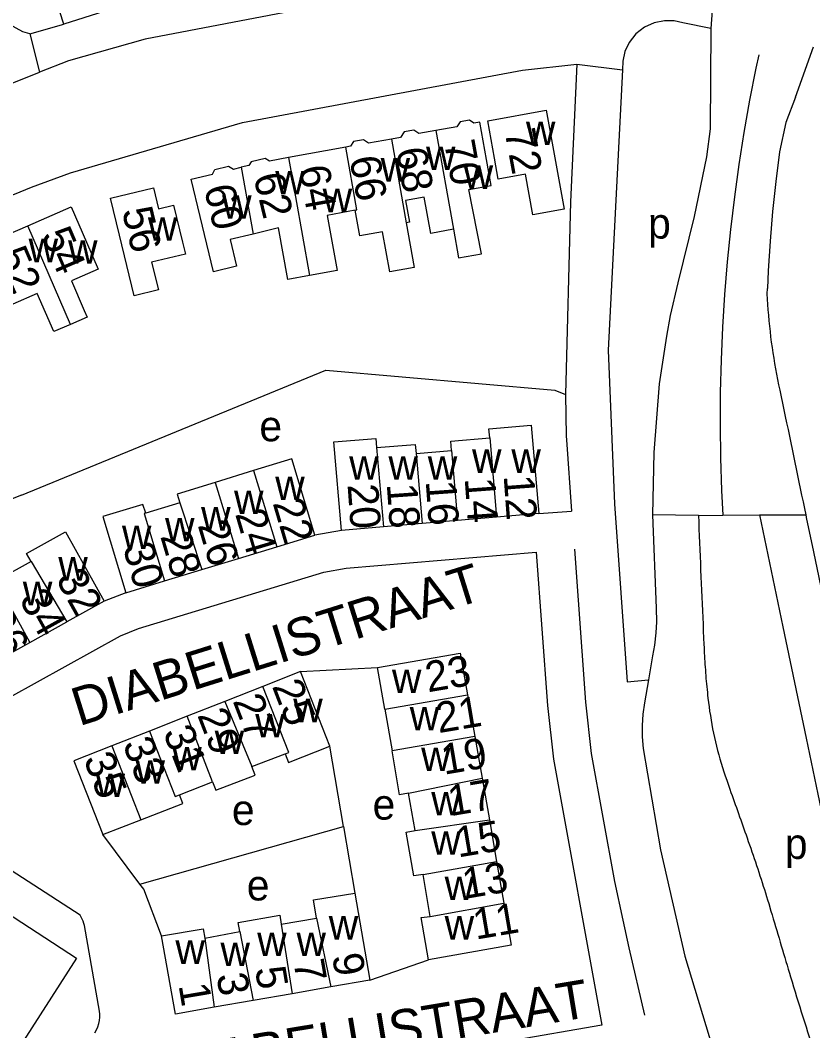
# Model space of a CAD drawing. Extents: x 159045 to 160918, y 380454 to 382516.
# Drawn here: x 160420.2 to 160524.1, y 381588.1 to 381720.5 of the extents above; entities that cross this region are included whole.
import ezdxf

# ---------------------------------------------------------------- set-up
doc = ezdxf.new("R2010")
doc.units = 0
for name, color, linetype in [('BLT_Basislijn', 7, 'Continuous'), ('BLT_Bebouwing', 7, 'Continuous'), ('BLT_Centroide', 7, 'Continuous'), ('BLT_Huisnummer', 7, 'Continuous'), ('BLT_Huisnummer_ tussenligend', 7, 'Continuous'), ('BLT_Onderverdeling_panden', 7, 'Continuous'), ('BLT_Straatnaam', 7, 'Continuous'), ('BLT_Vlakafsluiter', 7, 'Continuous')]:
    doc.layers.add(name, color=color, linetype=linetype)

msp = doc.modelspace()

# ---------------------------------------------------------------- linework, layer by layer
at = {"layer": 'BLT_Basislijn'}
for p, q in [((160510.75, 381719.44), (160507.06, 381720.16)), ((160421.42, 381718.73), (160422.69, 381713.7)), ((160521.87, 381710.43), (160524.19, 381717.05)), ((160491.67, 381671.47), (160491.79, 381666)), ((160503.25, 381663.87), (160503.08, 381655.7)), ((160488.18, 381655.86), (160492.48, 381656.18)), ((160509.11, 381655.6), (160512.3, 381655.63)), ((160512.3, 381655.63), (160517.12, 381655.67)), ((160462.29, 381653.66), (160458.83, 381653.04)), ((160434.02, 381645.49), (160431.17, 381644.36)), ((160456.94, 381635.14), (160467.03, 381635.68)), ((160502.58, 381634.08), (160502.03, 381631.05)), ((160502.03, 381631.05), (160501.84, 381629.56)), ((160378.5, 381629.28), (160427.57, 381597.58)), ((160501.84, 381629.56), (160501.74, 381628.07)), ((160501.74, 381628.07), (160501.73, 381626.58)), ((160501.73, 381626.58), (160501.85, 381625.08)), ((160462.58, 381614.83), (160460.78, 381625.37)), ((160435.88, 381607.3), (160462.58, 381614.83)), ((160462.58, 381614.83), (160464.08, 381606.11)), ((160498.12, 381607.65), (160499.22, 381602.56)), ((160427.57, 381597.58), (160417.9, 381582.6)), ((160466.03, 381594.7), (160473.73, 381597.38))]:
    msp.add_line(p, q, dxfattribs=at)
for points in [[(160421.42, 381718.73), (160420.52, 381718.98), (160408.42, 381725.7)], [(160463.62, 381723.22), (160463.38, 381723.18), (160436.55, 381718.05), (160426.52, 381715.2), (160422.69, 381713.7)], [(160421.42, 381718.73), (160425.89, 381719.98)], [(160507.06, 381720.16), (160505.92, 381720.42), (160504.65, 381720.45), (160503.33, 381720.18), (160502.05, 381719.6), (160500.92, 381718.72), (160500.05, 381717.62), (160499.47, 381716.4), (160499.19, 381715.17), (160499.16, 381714)], [(160510.75, 381719.44), (160510.64, 381706.3), (160510.17, 381702.62), (160508.56, 381694.79), (160506.43, 381686.1), (160505.43, 381681.83), (160504.93, 381679.13), (160503.97, 381672.88), (160503.25, 381663.87)], [(160517.02, 381715.99), (160516.64, 381714.23), (160515.82, 381710.03), (160515.08, 381705.81), (160514.41, 381701.59), (160513.83, 381697.35), (160513.32, 381693.09), (160512.9, 381688.84), (160512.55, 381684.57), (160512.28, 381680.3), (160512.09, 381676.02), (160511.99, 381671.74), (160511.96, 381667.46), (160512.01, 381663.18), (160512.15, 381658.9), (160512.3, 381655.63)], [(160343.13, 381655.19), (160349.63, 381659.57), (160374.12, 381676.49), (160389.16, 381685.3), (160421.65, 381698.65), (160426.75, 381700.5), (160449.33, 381707.1), (160486.03, 381713.96), (160493.16, 381714.78)], [(160493.16, 381714.78), (160492.34, 381696.72), (160491.67, 381671.47)], [(160373.77, 381692), (160385.73, 381698.91), (160422.69, 381713.7)], [(160499.16, 381714), (160497.27, 381677.29), (160498.11, 381657.12), (160499.79, 381633.79), (160502.58, 381634.08)], [(160521.87, 381710.43), (160520.56, 381707.13), (160519.74, 381703.25), (160519.26, 381699.36), (160518.85, 381695.47), (160518.52, 381691.56), (160518.27, 381687.65), (160518.17, 381685.37)], [(160519.83, 381672.03), (160519.68, 381672.73), (160519.54, 381673.42), (160519.4, 381674.11), (160519.27, 381674.81), (160519.15, 381675.51), (160519.03, 381676.21), (160518.92, 381676.91), (160518.82, 381677.61), (160518.72, 381678.31), (160518.63, 381679.02), (160518.55, 381679.72), (160518.47, 381680.43), (160518.4, 381681.13), (160518.34, 381681.84), (160518.28, 381682.55), (160518.23, 381683.25), (160518.19, 381683.96), (160518.15, 381684.67), (160518.17, 381685.37)], [(160420.33, 381658.28), (160460.24, 381674.67), (160490.28, 381672.01), (160491.67, 381671.47)], [(160523.24, 381655.68), (160523.06, 381656.54), (160522.88, 381657.4), (160522.7, 381658.26), (160522.52, 381659.13), (160522.34, 381659.99), (160522.16, 381660.85), (160521.98, 381661.71), (160521.8, 381662.57), (160521.62, 381663.43), (160521.45, 381664.29), (160521.27, 381665.15), (160521.09, 381666.01), (160520.91, 381666.87), (160520.73, 381667.73), (160520.55, 381668.59), (160520.37, 381669.45), (160520.19, 381670.31), (160520.01, 381671.17), (160519.83, 381672.03)], [(160491.79, 381666), (160491.8, 381665.54), (160492.48, 381656.18)], [(160420.33, 381658.28), (160407.99, 381653.36), (160398.29, 381648.34), (160390.1, 381643.2)], [(160503.08, 381655.7), (160503.57, 381643.44), (160503.62, 381641.68), (160503.53, 381640.24), (160503.36, 381638.59), (160503.09, 381637.23), (160502.58, 381634.08)], [(160509.11, 381655.6), (160509.15, 381654.71), (160509.19, 381653.82), (160509.22, 381652.93), (160509.26, 381652.04), (160509.3, 381651.14), (160509.34, 381650.25), (160509.38, 381649.36), (160509.41, 381648.47), (160509.45, 381647.58), (160509.49, 381646.69), (160509.53, 381645.8), (160509.57, 381644.91), (160509.61, 381644.02), (160509.64, 381643.13), (160509.68, 381642.24), (160509.72, 381641.35), (160509.76, 381640.46), (160509.8, 381639.57), (160509.84, 381638.68)], [(160517.12, 381655.67), (160518.65, 381648.35), (160520.18, 381641.03), (160521.71, 381633.72), (160523.24, 381626.4), (160524.77, 381619.09), (160526.3, 381611.77), (160527.13, 381607.83)], [(160532.93, 381609.3), (160532.82, 381609.86), (160532.7, 381610.42), (160532.58, 381610.98), (160532.47, 381611.54), (160532.35, 381612.1), (160532.23, 381612.67), (160531.26, 381617.32), (160529.86, 381624.02), (160528.46, 381630.72), (160527.06, 381637.42), (160525.66, 381644.12), (160524.26, 381650.83), (160523.31, 381655.33), (160523.29, 381655.46), (160523.26, 381655.58), (160523.24, 381655.68)], [(160492.85, 381651.18), (160494.32, 381631.15), (160495.06, 381624.39), (160498.12, 381607.65)], [(160386.88, 381639.33), (160407.89, 381625.76), (160433.31, 381639.83), (160435.69, 381640.78), (160460.01, 381648.17), (160462.92, 381648.69), (160487.86, 381650.82), (160489.34, 381630.7), (160490.11, 381623.67), (160496.47, 381588.81), (160472.24, 381584.61), (160444.49, 381579.75), (160425.82, 381576.36), (160425.81, 381576.36), (160423.42, 381575.08), (160418.36, 381568.45)], [(160509.84, 381638.68), (160509.85, 381638.31), (160509.87, 381637.94), (160509.89, 381637.57), (160509.91, 381637.2), (160509.93, 381636.83), (160509.95, 381636.47), (160509.97, 381636.1), (160510, 381635.73), (160510.03, 381635.36), (160510.05, 381634.99), (160510.08, 381634.62), (160510.11, 381634.25), (160510.15, 381633.89), (160510.18, 381633.52), (160510.22, 381633.15), (160510.25, 381632.78), (160510.29, 381632.42), (160510.33, 381632.05), (160510.37, 381631.68)], [(160429.96, 381587.81), (160430.18, 381588.2), (160430.35, 381588.6), (160430.47, 381589.02), (160430.56, 381589.43), (160430.61, 381589.85), (160430.61, 381590.26), (160430.58, 381590.65), (160428.59, 381601.85), (160428.53, 381602.14), (160428.44, 381602.43), (160428.32, 381602.71), (160428.19, 381602.98), (160428.03, 381603.24), (160381.73, 381633.15)], [(160510.37, 381631.68), (160510.44, 381631.1), (160510.51, 381630.53), (160510.59, 381629.95), (160510.68, 381629.38), (160510.77, 381628.8), (160510.88, 381628.23), (160510.98, 381627.65), (160511.1, 381627.08), (160511.22, 381626.51), (160511.35, 381625.95), (160511.49, 381625.38), (160511.63, 381624.81), (160511.78, 381624.25), (160511.94, 381623.69), (160512.1, 381623.13), (160512.27, 381622.58), (160512.45, 381622.02), (160512.64, 381621.47), (160512.83, 381620.92)], [(160501.85, 381625.08), (160504.13, 381611.77), (160507.35, 381597.84)], [(160512.83, 381620.92), (160512.97, 381620.52), (160513.11, 381620.12), (160513.25, 381619.72), (160513.39, 381619.32), (160513.53, 381618.92), (160513.67, 381618.53), (160513.81, 381618.13), (160513.95, 381617.73), (160514.1, 381617.33), (160514.24, 381616.93), (160514.38, 381616.53), (160514.52, 381616.13), (160514.66, 381615.73), (160514.8, 381615.33), (160514.94, 381614.93), (160515.08, 381614.53), (160515.22, 381614.13), (160515.36, 381613.74), (160515.51, 381613.34)], [(160435.88, 381607.3), (160431.02, 381613.79)], [(160515.51, 381613.34), (160515.66, 381612.89), (160515.82, 381612.44), (160515.98, 381611.99), (160516.13, 381611.54), (160516.29, 381611.09), (160516.44, 381610.64), (160516.59, 381610.2), (160516.74, 381609.74), (160516.89, 381609.29), (160517.04, 381608.84), (160517.19, 381608.39), (160517.34, 381607.94), (160517.48, 381607.49), (160517.63, 381607.04), (160517.77, 381606.58), (160517.91, 381606.13), (160518.05, 381605.68), (160518.19, 381605.22), (160518.33, 381604.77)], [(160438.72, 381600.52), (160436.39, 381606.63), (160435.88, 381607.3)], [(160518.33, 381604.77), (160518.63, 381603.75), (160518.78, 381603.25), (160518.93, 381602.74), (160519.08, 381602.23), (160519.24, 381601.73), (160519.39, 381601.22), (160519.54, 381600.71), (160519.69, 381600.21), (160519.84, 381599.7), (160519.99, 381599.19), (160520.14, 381598.68), (160520.29, 381598.18), (160520.44, 381597.67), (160520.59, 381597.16), (160520.74, 381596.66), (160520.9, 381596.15), (160521.05, 381595.64), (160521.2, 381595.14)], [(160499.22, 381602.56), (160500, 381598.96), (160502.04, 381590.1)], [(160507.35, 381597.84), (160513.26, 381578.22), (160519.72, 381558.71)], [(160521.2, 381595.14), (160521.4, 381594.48), (160521.6, 381593.82), (160521.8, 381593.16), (160522, 381592.5), (160522.2, 381591.85), (160522.41, 381591.19), (160522.61, 381590.54), (160522.82, 381589.88), (160523.03, 381589.22), (160523.23, 381588.57), (160523.44, 381587.91), (160523.65, 381587.26), (160523.86, 381586.6), (160524.07, 381585.95), (160524.28, 381585.3), (160524.5, 381584.64), (160524.71, 381583.99), (160524.93, 381583.34), (160525.61, 381581.26)]]:
    msp.add_lwpolyline(points, dxfattribs=at)
at = {"layer": 'BLT_Bebouwing'}
for p, q in [((160462.86, 381703.88), (160455.38, 381702.52)), ((160415.8, 381691.26), (160421.19, 381693.58)), ((160470.81, 381693.96), (160471.86, 381688.12)), ((160472.09, 381663.74), (160476.74, 381664.14)), ((160450.78, 381661.49), (160445.76, 381659.95)), ((160441.09, 381657.27), (160436.64, 381655.92)), ((160477.52, 381654.95), (160472.87, 381654.56)), ((160482.64, 381655.39), (160477.52, 381654.95)), ((160472.87, 381654.56), (160467.8, 381654.12)), ((160448.8, 381649.99), (160453.81, 381651.51)), ((160421.6, 381649.59), (160416.99, 381647.03)), ((160443.98, 381648.52), (160448.8, 381649.99)), ((160439.11, 381647.04), (160443.98, 381648.52)), ((160431.17, 381644.36), (160426.31, 381641.67)), ((160421.45, 381638.98), (160426.31, 381641.67)), ((160416.6, 381636.29), (160421.45, 381638.98)), ((160451.98, 381633.19), (160447.03, 381631.24)), ((160447.03, 381631.24), (160442.08, 381629.3)), ((160478.83, 381632.1), (160479.79, 381626.63)), ((160467.98, 381630.22), (160468.94, 381624.75)), ((160442.08, 381629.3), (160437.13, 381627.35)), ((160437.13, 381627.35), (160432.18, 381625.41)), ((160479.79, 381626.63), (160480.74, 381621.17)), ((160450.55, 381622.69), (160454.91, 381624.36)), ((160441.05, 381618.99), (160445.39, 381620.68)), ((160480.74, 381621.17), (160481.7, 381615.71)), ((160481.7, 381615.71), (160482.65, 381610.24)), ((160482.65, 381610.24), (160483.61, 381604.78)), ((160473.92, 381603.06), (160473, 381608.57)), ((160454.42, 381602.03), (160459.02, 381602.85)), ((160444.39, 381600.21), (160448.98, 381601.06)), ((160455.83, 381592.92), (160450.72, 381592.04)), ((160460.93, 381593.81), (160455.83, 381592.92)), ((160450.72, 381592.04), (160445.62, 381591.15))]:
    msp.add_line(p, q, dxfattribs=at)
for points in [[(160425.89, 381719.98), (160424.38, 381724.75), (160423.3, 381728.18)], [(160431.37, 381721.7), (160431.14, 381721.64), (160425.89, 381719.98)], [(160487.41, 381695.02), (160486.45, 381700.33), (160482.87, 381699.67), (160482.37, 381702.43), (160481.48, 381707.35), (160489.16, 381708.75), (160491.52, 381695.77), (160487.41, 381695.02)], [(160477.02, 381693.12), (160477.65, 381689.37), (160480.68, 381689.92), (160478.99, 381698.32), (160481.95, 381698.85), (160481.33, 381702.26), (160480.43, 381707.17), (160479.68, 381707.04), (160479.09, 381707.44), (160477.88, 381707.22), (160477.42, 381706.56), (160474.7, 381706.06)], [(160474.7, 381706.06), (160472.46, 381705.65), (160471.8, 381706.11), (160470.52, 381705.88), (160470.03, 381705.16), (160468.88, 381704.95)], [(160468.88, 381704.95), (160465.87, 381704.4), (160465.21, 381704.86), (160463.9, 381704.62), (160463.47, 381703.99), (160462.86, 381703.88)], [(160455.38, 381702.52), (160452.85, 381702.06), (160452.28, 381702.41), (160450.46, 381701.97), (160450.14, 381701.49), (160449.14, 381701.25)], [(160450.71, 381692.49), (160447.69, 381691.76), (160448.54, 381688.27), (160445.54, 381687.54), (160443.77, 381694.81), (160442.6, 381699.67), (160445.41, 381700.35), (160445.7, 381700.95), (160447.51, 381701.39), (160448.13, 381701), (160449.14, 381701.25)], [(160441.47, 381691.43), (160441.85, 381689.86), (160437.41, 381688.79), (160438.29, 381685.16), (160435.11, 381684.39), (160433.19, 381692.33), (160432.01, 381697.18), (160437.66, 381698.56), (160438.33, 381695.81), (160440.29, 381696.29), (160441.47, 381691.43)], [(160477.02, 381693.12), (160474.02, 381692.58), (160473.15, 381697.32), (160470.7, 381696.87), (160471.21, 381694.03), (160470.81, 381693.96)], [(160421.19, 381693.58), (160426.88, 381696.04), (160428.86, 381691.45), (160430.39, 381687.89), (160426.89, 381686.38), (160428.58, 381682.48), (160428.96, 381681.6), (160426.77, 381680.65)], [(160464.1, 381695.61), (160460.41, 381694.94), (160461.73, 381687.71), (160458.11, 381687.05)], [(160471.86, 381688.12), (160468.63, 381687.53), (160467.67, 381692.78), (160464.71, 381692.26), (160464.1, 381695.61)], [(160458.11, 381687.05), (160455.28, 381686.53), (160454.04, 381693.3), (160450.71, 381692.49)], [(160426.77, 381680.65), (160424.57, 381679.71), (160422.42, 381684.71), (160419.2, 381683.32)], [(160481.76, 381665.77), (160481.65, 381666.98), (160487.19, 381667.43), (160488.18, 381655.86)], [(160462.29, 381653.66), (160461.32, 381665.24), (160466.82, 381665.7), (160466.92, 381664.51)], [(160476.74, 381664.14), (160476.65, 381665.33), (160481.76, 381665.77)], [(160466.92, 381664.51), (160471.99, 381664.93), (160472.09, 381663.74)], [(160458.83, 381653.04), (160455.79, 381663.02), (160450.78, 381661.49)], [(160445.76, 381659.95), (160440.75, 381658.42), (160441.09, 381657.27)], [(160436.64, 381655.92), (160436.27, 381657.06), (160430.99, 381655.47), (160434.02, 381645.49)], [(160488.18, 381655.86), (160482.64, 381655.39)], [(160467.8, 381654.12), (160462.29, 381653.66)], [(160421.6, 381649.59), (160421.02, 381650.64), (160426.12, 381653.46), (160431.17, 381644.36)], [(160453.81, 381651.51), (160458.83, 381653.04)], [(160434.02, 381645.49), (160439.11, 381647.04), (160439.11, 381647.04)], [(160467.03, 381635.68), (160477.88, 381637.56), (160478.83, 381632.1)], [(160456.94, 381635.14), (160451.98, 381633.19)], [(160460.78, 381625.37), (160456.94, 381635.14)], [(160467.98, 381630.22), (160467.03, 381635.68)], [(160432.18, 381625.41), (160427.23, 381623.46), (160431.02, 381613.79)], [(160454.91, 381624.36), (160455.34, 381623.24), (160460.78, 381625.37)], [(160471.11, 381619.2), (160469.93, 381618.99), (160468.94, 381624.75)], [(160445.39, 381620.68), (160445.82, 381619.59), (160450.98, 381621.57), (160450.55, 381622.69), (160450.55, 381622.69)], [(160471.98, 381614.31), (160471.11, 381619.2)], [(160435.99, 381615.73), (160441.49, 381617.87), (160441.05, 381618.99)], [(160431.02, 381613.79), (160435.99, 381615.73)], [(160473, 381608.57), (160471.81, 381608.36), (160470.8, 381614.1), (160471.98, 381614.31)], [(160459.02, 381602.85), (160458.62, 381605.21), (160464.08, 381606.11)], [(160464.08, 381606.11), (160466.03, 381594.7)], [(160483.61, 381604.78), (160484.56, 381599.31), (160473.73, 381597.38)], [(160448.98, 381601.06), (160448.78, 381602.26), (160454.21, 381603.22), (160454.42, 381602.03)], [(160473.73, 381597.38), (160472.76, 381602.9), (160473.92, 381603.06)], [(160438.72, 381600.52), (160444.18, 381601.45), (160444.39, 381600.21)], [(160445.62, 381591.15), (160440.52, 381590.26), (160438.72, 381600.52)], [(160466.03, 381594.7), (160460.93, 381593.81)]]:
    msp.add_lwpolyline(points, dxfattribs=at)
at = {"layer": 'BLT_Onderverdeling_panden'}
for p, q in [((160474.7, 381706.06), (160477.02, 381693.12)), ((160468.88, 381704.95), (160470.81, 381693.96)), ((160455.38, 381702.52), (160458.11, 381687.05)), ((160449.14, 381701.25), (160450.71, 381692.49)), ((160426.77, 381680.65), (160421.19, 381693.58)), ((160481.76, 381665.77), (160482.64, 381655.39)), ((160466.92, 381664.51), (160467.8, 381654.12)), ((160472.09, 381663.74), (160472.87, 381654.56)), ((160450.78, 381661.49), (160453.81, 381651.51)), ((160445.76, 381659.95), (160448.8, 381649.99)), ((160441.09, 381657.27), (160443.98, 381648.52)), ((160421.6, 381649.59), (160426.31, 381641.67)), ((160416.99, 381647.03), (160421.45, 381638.98)), ((160447.03, 381631.24), (160450.55, 381622.69)), ((160467.98, 381630.22), (160478.83, 381632.1)), ((160445.39, 381620.68), (160442.08, 381629.3)), ((160479.79, 381626.63), (160468.94, 381624.75)), ((160432.18, 381625.41), (160435.99, 381615.73)), ((160471.11, 381619.2), (160480.74, 381621.17)), ((160471.98, 381614.31), (160481.7, 381615.71)), ((160473, 381608.57), (160482.65, 381610.24)), ((160473.92, 381603.06), (160483.61, 381604.78)), ((160454.42, 381602.03), (160455.83, 381592.92)), ((160459.02, 381602.85), (160460.93, 381593.81)), ((160448.98, 381601.06), (160450.72, 381592.04)), ((160444.39, 381600.21), (160445.62, 381591.15))]:
    msp.add_line(p, q, dxfattribs=at)
for points in [[(160464.1, 381695.61), (160464.31, 381695.65), (160462.86, 381703.88)], [(160476.74, 381664.14), (160477.52, 381654.95), (160477.52, 381654.95)], [(160436.64, 381655.92), (160436.43, 381655.85), (160439.11, 381647.04)], [(160454.91, 381624.36), (160455.39, 381624.55), (160451.98, 381633.19)], [(160437.13, 381627.35), (160440.49, 381618.77), (160441.05, 381618.99), (160441.05, 381618.99)]]:
    msp.add_lwpolyline(points, dxfattribs=at)
at = {"layer": 'BLT_Vlakafsluiter'}
for p, q in [((160493.16, 381714.78), (160499.16, 381714)), ((160509.11, 381655.6), (160503.08, 381655.7)), ((160517.12, 381655.67), (160523.24, 381655.68))]:
    msp.add_line(p, q, dxfattribs=at)
msp.add_lwpolyline([(160513.26, 381732.37), (160510.96, 381722.35), (160510.75, 381719.44)], dxfattribs=at)

# ---------------------------------------------------------------- texts
at = {"layer": 'BLT_Centroide'}
for s, p in [('w', (160486.5, 381704.16)), ('w', (160473.39, 381700.89)), ('w', (160467.44, 381699.38)), ('w', (160478.33, 381698.41)), ('w', (160453.62, 381697.69)), ('w', (160446.66, 381694.5)), ('w', (160459.84, 381695.36)), ('w', (160436.92, 381691.61)), ('p', (160502.52, 381691.9)), ('w', (160421.28, 381688.8)), ('w', (160426.45, 381688.61)), ('e', (160451.54, 381665.33)), ('w', (160479.43, 381661.19)), ('w', (160484.59, 381661.19)), ('w', (160463.32, 381660.28)), ('w', (160468.47, 381660.28)), ('w', (160473.63, 381660.28)), ('w', (160453.62, 381657.62)), ('w', (160448.22, 381655.79)), ('w', (160443.9, 381653.63)), ('w', (160439.17, 381652.22)), ('w', (160433.52, 381651.22)), ('w', (160425.17, 381647.08)), ('w', (160420.52, 381643.84)), ('w', (160468.93, 381632.33)), ('w', (160455.98, 381628.51)), ('w', (160471.26, 381627.43)), ('w', (160451, 381626.51)), ('w', (160445.68, 381624.35)), ('w', (160440.12, 381622.19)), ('w', (160472.75, 381622.11)), ('w', (160435.3, 381620.44)), ('w', (160430.07, 381618.7)), ('w', (160474.08, 381616.29)), ('e', (160447.94, 381615.03)), ('e', (160466.39, 381615.74)), ('w', (160474.08, 381611.13)), ('p', (160520.45, 381610.59)), ('e', (160449.89, 381605.15)), ('w', (160475.84, 381605.19)), ('w', (160460.64, 381600.03)), ('w', (160475.84, 381600.03)), ('w', (160451.25, 381597.87)), ('w', (160456.41, 381597.87)), ('w', (160440.53, 381596.84)), ('w', (160446.44, 381596.54))]:
    msp.add_text(s, height=4, dxfattribs=at).set_placement(p)
at = {"layer": 'BLT_Huisnummer'}
for s, rotation, p in [('72', 280.3254, (160483.69, 381705.97)), ('68', 280.3299, (160469.43, 381703.53)), ('64', 280.3232, (160456.7, 381701.19)), ('60', 283.6732, (160444.24, 381698.52)), ('56', 283.6526, (160433.49, 381695.57)), ('54', 293.3231, (160422.88, 381692.36)), ('12', 274.1174, (160483.57, 381660.81)), ('20', 274.1174, (160463.1, 381659.64)), ('16', 274.1174, (160473.35, 381660.1)), ('22', 286.5174, (160453.26, 381657.25)), ('26', 286.5174, (160443.43, 381654.36)), ('30', 286.5174, (160433.6, 381651.44)), ('32', 299.1174, (160424.78, 381647.26)), ('36', 299.1174, (160415.16, 381641.94)), ('23', 9.6174, (160473.64, 381632.42)), ('25', 291.1174, (160453.16, 381633.24)), ('29', 291.1174, (160443.36, 381629.46)), ('33', 291.1174, (160433.57, 381625.67)), ('19', 9.6174, (160475.76, 381621.62)), ('35', 291.1174, (160428.44, 381623.69)), ('15', 9.6174, (160477.6, 381610.77)), ('11', 9.6174, (160479.92, 381600.01)), ('9', 279.6174, (160461.06, 381597.93)), ('5', 279.6174, (160450.95, 381596.22)), ('1', 279.6174, (160440.93, 381594.03))]:
    msp.add_text(s, height=4, rotation=rotation, dxfattribs=at).set_placement(p)
at = {"layer": 'BLT_Huisnummer_ tussenligend'}
for s, rotation, p in [('70', 280.3299, (160475.76, 381704.47)), ('66', 280.3232, (160463.34, 381702.42)), ('62', 283.6732, (160450.73, 381700.05)), ('52', 293.3277, (160417.06, 381689.82)), ('14', 274.1174, (160478.46, 381660.46)), ('18', 274.1174, (160468.24, 381659.72)), ('24', 286.5174, (160448.34, 381655.82)), ('28', 286.5174, (160438.52, 381652.9)), ('34', 299.1174, (160419.97, 381644.61)), ('27', 291.1174, (160448.01, 381631.31)), ('21', 9.6174, (160475.04, 381627.07)), ('31', 291.1174, (160438.87, 381627.2)), ('17', 9.6174, (160476.62, 381616.19)), ('13', 9.6174, (160478.52, 381605.35)), ('7', 279.6174, (160456, 381597.13)), ('3', 279.6174, (160445.9, 381595.36))]:
    msp.add_text(s, height=4, rotation=rotation, dxfattribs=at).set_placement(p)
at = {"layer": 'BLT_Straatnaam'}
for rotation, p in [(17.4034, (160427.9, 381627.97)), (9.4034, (160439.99, 381580.8))]:
    msp.add_text('DIABELLISTRAAT', height=5, rotation=rotation, dxfattribs=at).set_placement(p)

doc.saveas('drawing.dxf')
